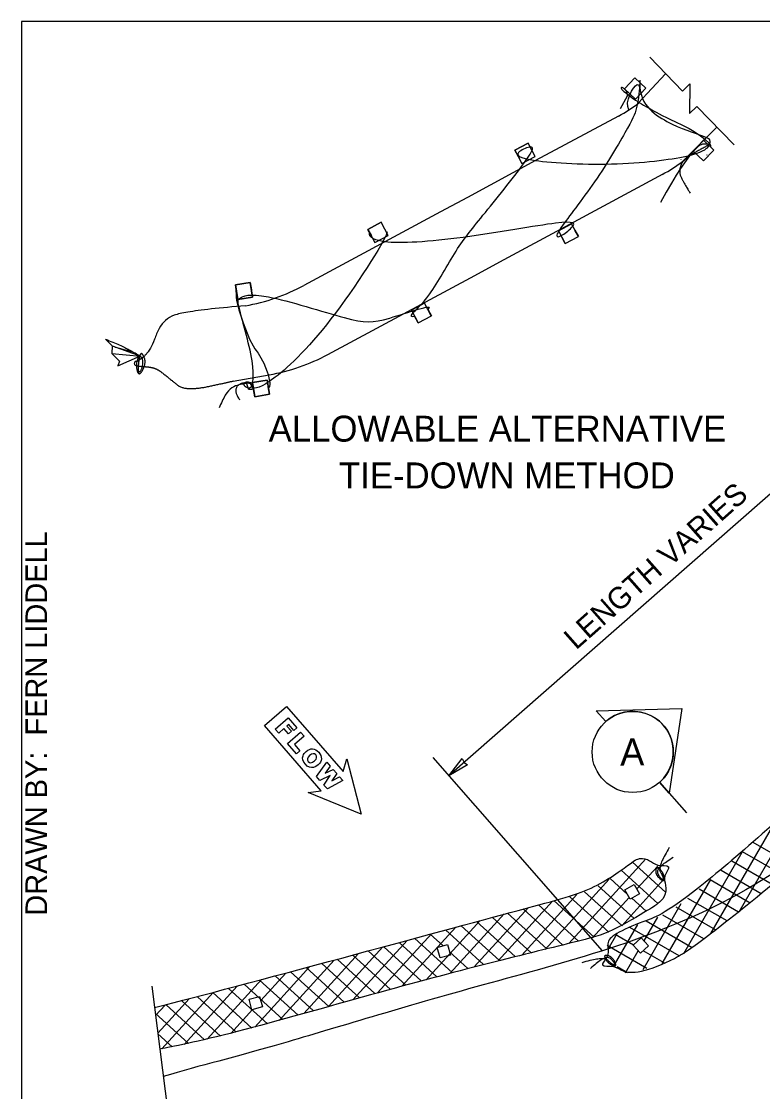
# Model space of a CAD drawing. Extents: x 99862 to 103680, y 99470 to 102076.
# Drawn here: x 99862 to 100410, y 101285 to 102076 of the extents above; entities that cross this region are included whole.
import ezdxf

# ---------------------------------------------------------------- set-up
doc = ezdxf.new("R2010")
doc.units = 0
for name, color, linetype in [('Level 1', 7, 'Continuous'), ('Level 10', 7, 'Continuous'), ('Level 15', 7, 'Continuous'), ('Level 20', 7, 'Continuous'), ('Level 4', 7, 'Continuous'), ('Level 6', 7, 'Continuous'), ('Level 62', 7, 'Continuous'), ('Level 8', 7, 'Continuous'), ('Level 9', 7, 'Continuous')]:
    doc.layers.add(name, color=color, linetype=linetype)

msp = doc.modelspace()

# ---------------------------------------------------------------- linework, layer by layer
at = {"layer": 'Level 1'}
msp.add_lwpolyline([(99862, 99999.5), (103151, 99999.5), (103151, 102075.5), (99862, 102075.5)], close=True, dxfattribs=at)
at = {"layer": 'Level 10'}
for p, q in [((100368.79, 101976.38), (100368.57, 101976.77)), ((100368.79, 101976.38), (100368.79, 101976.38)), ((100349.23, 101973.52), (100349.45, 101973.13)), ((100349.23, 101973.52), (100349.45, 101973.13)), ((100349.45, 101973.13), (100349.45, 101973.13))]:
    msp.add_line(p, q, dxfattribs=at)
for points in [[(100528.6, 101581.63), (100528.11, 101581.18), (100470.66, 101529.07), (100345.88, 101417.9), (100320.67, 101410.22), (100299.49, 101400.95), (100293.76, 101394.13), (100297.49, 101385.18), (100287.56, 101376.44), (100301.23, 101377.9), (100305.39, 101373.25), (100317.46, 101371.44), (100346.05, 101382.29), (100366.25, 101397.24), (100420.98, 101439.69), (100505.45, 101518.02), (100543.69, 101552.46), (100550.6, 101557.88)], [(99960.3, 101346.71), (99980.01, 101351.44), (100092.18, 101381.29), (100240.54, 101421.79), (100285.43, 101432.91), (100315.52, 101456.07), (100317.68, 101456.61), (100319.54, 101456.89)], [(100319.54, 101456.89), (100321.4, 101457.18), (100327.05, 101455.43), (100330.93, 101450.99), (100343.75, 101452.25), (100335.73, 101443.71), (100338.68, 101437.44), (100338.07, 101428.1), (100331.65, 101422.87), (100329.52, 101421.23), (100296.85, 101401.65), (100277.56, 101396.49), (100203.1, 101378.53), (100118.18, 101355.67), (100007.39, 101324.13), (99968.74, 101316.73), (99964.23, 101315.82)], [(100683.65, 101336.86), (100679.43, 101333.35), (100655.62, 101316.88), (100531.24, 101226.43), (100387.02, 101132.84), (100378.6, 101128.6), (100349.84, 101116.39), (100347.55, 101104.92), (100340.78, 101099.98), (100337.73, 101096.69), (100347.02, 101095.39), (100349.87, 101092.19), (100366.06, 101083.31), (100391.52, 101093.94), (100413.21, 101106.63), (100472.21, 101142.93), (100564.63, 101211.69), (100635.94, 101263.16), (100694, 101302.8), (100704.56, 101309.85)]]:
    msp.add_open_spline(points, degree=3, dxfattribs=at)
at = {"layer": 'Level 15'}
for p, q in [((100502.21, 101802.28), (100177.84, 101517.98)), ((100165.97, 101531.51), (100291.31, 101388.51))]:
    msp.add_line(p, q, dxfattribs=at)
for points in [[(100326.33, 102048.97), (100350.5, 102023.87), (100356.07, 102029.24), (100355.66, 102007.34), (100361.24, 102012.71), (100388.7, 101984.19)], [(99958.3, 101362.49), (99980, 101191.8), (99995.36, 101193.75), (99968.54, 101159.12), (99983.9, 101161.08), (100038.72, 100729.93)]]:
    msp.add_lwpolyline(points, dxfattribs=at)
msp.add_lwpolyline([(100177.84, 101517.98), (100187.64, 101530.65), (100189.12, 101527.85), (100191.7, 101526.01)], close=True, dxfattribs=at)
at = {"layer": 'Level 20'}
for p, q in [((100286.85, 101565.92), (100350.05, 101567.69)), ((100286.85, 101565.92), (100350.05, 101567.69)), ((100293.89, 101557.98), (100286.85, 101565.92)), ((100293.89, 101557.98), (100286.85, 101565.92)), ((100350.05, 101567.69), (100340.73, 101505.16)), ((100350.05, 101567.69), (100340.73, 101505.16)), ((100340.73, 101505.16), (100333.69, 101513.09)), ((100333.69, 101513.09), (100353.6, 101490.65)), ((100340.73, 101505.16), (100333.69, 101513.09)), ((100333.69, 101513.09), (100353.6, 101490.65))]:
    msp.add_line(p, q, dxfattribs=at)
for points in [[(100113.09, 101489.44), (100073.88, 101505.56), (100083.56, 101506.82), (100041.56, 101554.98), (100057.89, 101569.22), (100099.89, 101521.06), (100102.46, 101530.48), (100113.09, 101489.44)], [(100113.09, 101489.44), (100073.88, 101505.56), (100083.56, 101506.82), (100041.56, 101554.98), (100057.89, 101569.22), (100099.89, 101521.06), (100102.46, 101530.48), (100113.09, 101489.44)], [(100059.21, 101560.74), (100065.66, 101553.35), (100063.44, 101551.41), (100059.57, 101555.85), (100058.27, 101554.72), (100061.66, 101550.84), (100059.44, 101548.9), (100056.06, 101552.79), (100052.17, 101549.4), (100049.59, 101552.36), (100059.21, 101560.74)], [(100059.21, 101560.74), (100065.66, 101553.35), (100063.44, 101551.41), (100059.57, 101555.85), (100058.27, 101554.72), (100061.66, 101550.84), (100059.44, 101548.9), (100056.06, 101552.79), (100052.17, 101549.4), (100049.59, 101552.36), (100059.21, 101560.74)], [(100068.37, 101550.23), (100070.95, 101547.27), (100063.74, 101540.99), (100067.78, 101536.36), (100065.37, 101534.27), (100058.76, 101541.85), (100068.37, 101550.23)], [(100068.37, 101550.23), (100070.95, 101547.27), (100063.74, 101540.99), (100067.78, 101536.36), (100065.37, 101534.27), (100058.76, 101541.85), (100068.37, 101550.23)], [(100081.74, 101535.28), (100082.65, 101534.07), (100083.27, 101532.87), (100083.62, 101531.66), (100083.68, 101530.44), (100083.46, 101529.25), (100082.98, 101528.11), (100082.21, 101527.02), (100081.19, 101525.98), (100079.52, 101524.78), (100077.92, 101524.13), (100076.35, 101523.98), (100074.8, 101524.3), (100073.3, 101525.12), (100071.86, 101526.45), (100070.69, 101528.06), (100070.03, 101529.6), (100069.85, 101531.16), (100070.17, 101532.77), (100070.51, 101533.58), (100071, 101534.38), (100071.63, 101535.15), (100072.41, 101535.89), (100073.59, 101536.79), (100074.79, 101537.4), (100076, 101537.73), (100077.23, 101537.79), (100078.43, 101537.57), (100079.59, 101537.08), (100080.69, 101536.31), (100081.74, 101535.28)], [(100081.74, 101535.28), (100082.65, 101534.07), (100083.27, 101532.87), (100083.62, 101531.66), (100083.68, 101530.44), (100083.46, 101529.25), (100082.98, 101528.11), (100082.21, 101527.02), (100081.19, 101525.98), (100079.52, 101524.78), (100077.92, 101524.13), (100076.35, 101523.98), (100074.8, 101524.3), (100073.3, 101525.12), (100071.86, 101526.45), (100070.69, 101528.06), (100070.03, 101529.6), (100069.85, 101531.16), (100070.17, 101532.77), (100070.51, 101533.58), (100071, 101534.38), (100071.63, 101535.15), (100072.41, 101535.89), (100073.59, 101536.79), (100074.79, 101537.4), (100076, 101537.73), (100077.23, 101537.79), (100078.43, 101537.57), (100079.59, 101537.08), (100080.69, 101536.31), (100081.74, 101535.28)], [(100080.1, 101532.36), (100079.52, 101533.35), (100078.64, 101534.03), (100077.6, 101534.25), (100076.38, 101533.91), (100074.98, 101532.94), (100073.83, 101531.69), (100073.34, 101530.54), (100073.42, 101529.47), (100073.99, 101528.49), (100074.9, 101527.76), (100075.93, 101527.54), (100077.16, 101527.91), (100078.67, 101528.98), (100079.74, 101530.16), (100080.19, 101531.29), (100080.1, 101532.36)], [(100080.1, 101532.36), (100079.52, 101533.35), (100078.64, 101534.03), (100077.6, 101534.25), (100076.38, 101533.91), (100074.98, 101532.94), (100073.83, 101531.69), (100073.34, 101530.54), (100073.42, 101529.47), (100073.99, 101528.49), (100074.9, 101527.76), (100075.93, 101527.54), (100077.16, 101527.91), (100078.67, 101528.98), (100079.74, 101530.16), (100080.19, 101531.29), (100080.1, 101532.36)], [(100097.13, 101517.26), (100099.51, 101514.54), (100088.13, 101508.17), (100085.58, 101511.1), (100090.15, 101518.07), (100082.63, 101514.48), (100080.09, 101517.4), (100087.83, 101527.92), (100090.3, 101525.09), (100086.41, 101519.8), (100092.41, 101522.67), (100095.01, 101519.69), (100091.36, 101514.12), (100097.13, 101517.26)], [(100097.13, 101517.26), (100099.51, 101514.54), (100088.13, 101508.17), (100085.58, 101511.1), (100090.15, 101518.07), (100082.63, 101514.48), (100080.09, 101517.4), (100087.83, 101527.92), (100090.3, 101525.09), (100086.41, 101519.8), (100092.41, 101522.67), (100095.01, 101519.69), (100091.36, 101514.12), (100097.13, 101517.26)]]:
    msp.add_lwpolyline(points, dxfattribs=at)
msp.add_circle((100313.79, 101535.54), 30, dxfattribs=at)
msp.add_circle((100313.79, 101535.54), 30, dxfattribs=at)
msp.add_arc((100313.79, 101535.54), 30, 311.56202, 131.56645, dxfattribs=at)
msp.add_arc((100313.79, 101535.54), 30, 311.56202, 131.56645, dxfattribs=at)
at = {"layer": 'Level 4'}
for p, q in [((99929.04, 101835.59), (99950.3, 101828.19)), ((99928.77, 101830.16), (99949.94, 101828.09))]:
    msp.add_line(p, q, dxfattribs=at)
for points in [[(100304.69, 102011.18), (100309.84, 102020.58), (100309.91, 102021.75), (100309.69, 102022.69), (100308.84, 102024.07), (100307.55, 102025.62), (100306.91, 102026.25), (100305.96, 102026.72), (100305.47, 102026.61), (100305.31, 102026.44), (100305.22, 102026.07), (100305.62, 102025.24), (100306.62, 102024.29), (100307.3, 102023.75), (100308.47, 102022.88), (100309.71, 102021.96), (100310.34, 102021.48), (100312.23, 102019.98), (100314.4, 102018.34), (100315.84, 102017.34), (100317.61, 102016.18), (100318.64, 102015.53), (100320.38, 102014.47), (100321.65, 102013.71), (100324.44, 102012.09), (100325.93, 102011.25), (100329.06, 102009.51), (100331.22, 102008.33), (100335.6, 102006.02), (100338.86, 102004.37), (100341.23, 102003.2), (100345.78, 102001.03), (100350.07, 101998.99), (100355.38, 101996.3), (100357.87, 101994.9), (100362.99, 101991.57), (100365.9, 101989.38), (100367.54, 101988.01), (100369.98, 101985.68), (100370.96, 101984.42), (100371.2, 101983.91), (100371.23, 101983.03), (100370.97, 101982.47), (100370.97, 101982.47)], [(100020.68, 101877.51), (100020.65, 101877.46), (100020.59, 101876.64), (100020.58, 101876.05), (100020.59, 101874.43), (100020.78, 101871.38), (100021.01, 101869.48), (100021.62, 101866.15), (100022.07, 101864.28), (100022.63, 101862.28), (100024.07, 101857.83), (100025.9, 101852.77), (100030.6, 101840.58)], [(99924.25, 101840.61), (99929.04, 101835.59), (99928.77, 101830.16), (99934.48, 101824.37), (99933.14, 101820.82), (99950.07, 101828.32)], [(100030.6, 101840.58), (100033.23, 101835.64), (100034.62, 101833.42), (100035.42, 101832.24), (100036.86, 101830.22), (100038.97, 101826.91), (100040.25, 101824.56), (100041.05, 101822.97), (100042.48, 101819.74), (100043.67, 101816.57), (100044.32, 101814.53), (100045.22, 101810.77), (100045.52, 101808.34), (100045.54, 101807.29), (100045.3, 101805.58), (100045.04, 101804.94), (100044.59, 101804.45)]]:
    msp.add_lwpolyline(points, dxfattribs=at)
for points in [[(100307.94, 101433.6), (100314.84, 101437.65), (100318.89, 101430.75), (100311.99, 101426.7)], [(100314.19, 101392.71), (100320.13, 101398.06), (100325.49, 101392.12), (100319.54, 101386.76)], [(100169.28, 101391.08), (100177.01, 101393.15), (100179.09, 101385.43), (100171.36, 101383.35)], [(100030.31, 101352.7), (100038.03, 101354.77), (100040.11, 101347.05), (100032.39, 101344.97)]]:
    msp.add_lwpolyline(points, close=True, dxfattribs=at)
for points, degree in [([(100319.04, 102032.12), (100317.77, 102015.04), (100339.67, 101999.18), (100369.15, 101989.9), (100370.88, 101988.72), (100370.81, 101986.68)], 3), ([(100310.98, 102010.13), (100307.26, 102015.88), (100321.37, 102039.66), (100316.92, 102010.31), (100313.52, 102002.62), (100288.5, 101959.02), (100257.03, 101919.17), (100257.66, 101915.91), (100260.59, 101916.53), (100271.12, 101924.42), (100271.12, 101929.94), (100184.95, 101913.83), (100120.24, 101909.84), (100118.33, 101918.16), (100119.62, 101919.44)], 3), ([(100152.7, 101857.45), (100150.4, 101856.59), (100148.3, 101858.54), (100162.64, 101869.3), (100183.91, 101908.9), (100201.01, 101929.41), (100241.32, 101979.51), (100240.06, 101984.24), (100228.4, 101979.59), (100226.82, 101972.75), (100300, 101967.97), (100362.31, 101976.02), (100371.2, 101983.91), (100370.47, 101985.05), (100358.18, 101985.05), (100334.25, 101941.68)], 3), ([(100370.81, 101986.68), (100370.96, 101984.42), (100357.34, 101977.45), (100351.09, 101972.41), (100349.42, 101969.8), (100348.08, 101963.98), (100350.31, 101958.23), (100356.23, 101948.66)], 2), ([(100827.57, 101924.36), (100760.06, 101847.66), (100689.54, 101753.7), (100669.26, 101721.45), (100565.8, 101567.25), (100397.3, 101413.08), (100195.24, 101363.06), (100041.72, 101315.14), (99995.15, 101304.04), (99966.8, 101295.66)], 3), ([(100132.19, 101919.85), (100133.03, 101917.24), (100091.69, 101851.07), (100044.45, 101805.23), (100028.42, 101802.85), (100037.31, 101812.21), (100021.01, 101869.48), (100022.01, 101869.87), (100033.65, 101877.28), (100110.92, 101852.48), (100126.41, 101852.48), (100167.95, 101867.66), (100162.42, 101862.68)], 3), ([(100027.49, 101865.36), (99987.04, 101861.93), (99965.72, 101855.62), (99957.29, 101831.72), (99948.11, 101824.17), (99945.45, 101824.17), (99945.45, 101820.84), (99952.98, 101820.4), (99957.69, 101819.92), (99963.06, 101818.32), (99973.27, 101810.03), (99980.29, 101804.16), (99993.01, 101804.06), (100011.68, 101808.18), (100018.93, 101809.78)], 2), ([(99924.25, 101840.61), (99950.11, 101830.2), (99946.24, 101822.9), (99948.66, 101812.44), (99954.47, 101823.06), (99952.84, 101826.87)], 2), ([(99952.84, 101826.87), (99951.3, 101830.91), (99948.95, 101828.41), (99947.88, 101814.48), (99952.02, 101819.68), (99951.32, 101830.3), (99931.4, 101834.45)], 2), ([(100032.8, 101807.81), (100029.39, 101809), (100028.07, 101808.8), (100026.38, 101808.01), (100026.32, 101806.4), (100028.33, 101805.22), (100030.2, 101804.33), (100032.53, 101805.63), (100031.03, 101808.07), (100027.91, 101808.07), (100013.89, 101804.52), (100008.05, 101789.91)], 2), ([(100033.46, 101803.82), (100031.1, 101803.23), (100029.64, 101803.48), (100028.62, 101808.78), (100021.62, 101807.14), (100019.64, 101800.77), (100023.29, 101795.89)], 2), ([(101085.75, 101767.26), (100851.58, 101567.5), (100738.84, 101387.48), (100680.23, 101288.16), (100628.41, 101241.49), (100408.17, 101099.51), (100270.3, 101083.42), (100093.57, 101042.42), (100035.51, 101028.27), (100002.7, 101021.57)], 3), ([(100340.76, 101464.9), (100332.05, 101450.3), (100336.44, 101446.34), (100337.38, 101438.72), (100330.87, 101444.44), (100331.03, 101447.4)], 2), ([(100331.03, 101447.4), (100331.08, 101450.49), (100333.27, 101449.38), (100337.4, 101440.29), (100333.34, 101442.77), (100331.21, 101450.07), (100343.58, 101457.73)], 2), ([(100276.35, 101380.02), (100292.73, 101384.58), (100295.39, 101379.3), (100302.5, 101376.38), (100298.7, 101384.16), (100295.8, 101384.79)], 2), ([(100295.8, 101384.79), (100292.81, 101385.56), (100293.3, 101383.15), (100300.98, 101376.77), (100299.66, 101381.34), (100293.17, 101385.32), (100282.53, 101375.41)], 2)]:
    msp.add_open_spline(points, degree=degree, dxfattribs=at)
at = {"layer": 'Level 6'}
for p, q in [((100315.36, 102033.72), (100307.8, 102025.68)), ((100323.4, 102026.16), (100315.36, 102033.72)), ((100307.8, 102025.68), (100315.84, 102018.12)), ((100315.84, 102018.12), (100323.4, 102026.16)), ((100317.27, 102028.65), (100317.27, 102028.65)), ((100226.71, 101980.22), (100236.43, 101985.46)), ((100236.43, 101985.45), (100226.72, 101980.22)), ((100236.43, 101985.45), (100236.43, 101985.46)), ((100236.43, 101985.46), (100239.04, 101980.61)), ((100236.43, 101985.45), (100236.43, 101985.46)), ((100241.66, 101975.76), (100236.43, 101985.45)), ((100226.71, 101980.22), (100226.72, 101980.22)), ((100229.32, 101975.38), (100226.71, 101980.22)), ((100226.71, 101980.22), (100226.72, 101980.22)), ((100226.72, 101980.22), (100231.94, 101970.52)), ((100231.94, 101970.52), (100241.66, 101975.76)), ((100241.66, 101975.76), (100241.66, 101975.76)), ((100231.94, 101970.52), (100231.94, 101970.52)), ((100118.05, 101921.76), (100127.77, 101927)), ((100118.05, 101921.76), (100118.06, 101921.76)), ((100118.05, 101921.76), (100118.05, 101921.76)), ((100120.66, 101916.92), (100118.05, 101921.76)), ((100127.77, 101926.99), (100118.06, 101921.76)), ((100118.06, 101921.76), (100123.31, 101912)), ((100118.08, 101921.7), (100118.08, 101921.7)), ((100127.77, 101926.99), (100127.77, 101927)), ((100127.77, 101927), (100130.38, 101922.15)), ((100127.77, 101926.99), (100127.77, 101926.99)), ((100133.03, 101917.24), (100127.77, 101926.99)), ((100127.8, 101926.94), (100127.8, 101926.94)), ((100258.82, 101920.64), (100268.53, 101925.88)), ((100271, 101921.31), (100273.61, 101916.46)), ((100123.31, 101912), (100133.03, 101917.24)), ((100133.03, 101917.24), (100133.03, 101917.24)), ((100263.89, 101911.23), (100261.28, 101916.07)), ((100263.89, 101911.23), (100273.6, 101916.47)), ((100123.31, 101912), (100123.31, 101912)), ((100020.12, 101880.75), (100030.99, 101882.64)), ((100020.12, 101880.74), (100030.99, 101882.63)), ((100030.99, 101882.63), (100020.12, 101880.74)), ((100020.12, 101880.75), (100020.12, 101880.74)), ((100021.06, 101875.32), (100020.12, 101880.75)), ((100020.12, 101880.74), (100020.12, 101880.74)), ((100022.01, 101869.87), (100020.12, 101880.74)), ((100020.12, 101880.74), (100022.01, 101869.87)), ((100020.12, 101880.72), (100020.12, 101880.72)), ((100030.99, 101882.63), (100030.99, 101882.64)), ((100030.99, 101882.64), (100031.94, 101877.21)), ((100030.99, 101882.63), (100030.99, 101882.63)), ((100030.99, 101882.63), (100032.89, 101871.76)), ((100032.89, 101871.76), (100030.99, 101882.63)), ((100031, 101882.61), (100031, 101882.61)), ((100032.89, 101871.76), (100022.01, 101869.87)), ((100022.01, 101869.87), (100032.89, 101871.76)), ((100022.01, 101869.87), (100022.01, 101869.87)), ((100032.89, 101871.76), (100032.89, 101871.76)), ((100155.23, 101852.76), (100152.62, 101857.61)), ((100162.33, 101862.84), (100164.95, 101858)), ((100032.67, 101808.55), (100043.55, 101810.44)), ((100043.55, 101810.44), (100032.67, 101808.55)), ((100032.67, 101808.55), (100034.49, 101798.12)), ((100034.49, 101798.11), (100033.54, 101803.54)), ((100044.42, 101805.43), (100045.36, 101800)), ((100045.36, 101800.01), (100034.49, 101798.12)), ((100034.49, 101798.12), (100045.36, 101800.01)), ((100045.36, 101800.01), (100045.36, 101800.01))]:
    msp.add_line(p, q, dxfattribs=at)
for points in [[(100239.04, 101980.61), (100239.04, 101980.61), (100236.43, 101985.46)], [(100236.43, 101985.46), (100236.43, 101985.46), (100236.43, 101985.46)], [(100366.02, 101987.69), (100373.73, 101980.43), (100373.74, 101980.43), (100366.18, 101972.39), (100366.17, 101972.39), (100358.46, 101979.65), (100366.02, 101987.69)], [(100226.71, 101980.22), (100229.32, 101975.38), (100229.32, 101975.38)], [(100226.71, 101980.22), (100226.71, 101980.22), (100226.71, 101980.22)], [(100118.05, 101921.76), (100120.66, 101916.92), (100120.66, 101916.92)], [(100130.38, 101922.15), (100130.38, 101922.15), (100127.77, 101926.99)], [(100258.82, 101920.64), (100263.89, 101911.23), (100263.89, 101911.23), (100273.61, 101916.46), (100273.6, 101916.47), (100268.53, 101925.88), (100258.82, 101920.64)], [(100258.82, 101920.64), (100258.82, 101920.64), (100263.89, 101911.23), (100263.89, 101911.23)], [(100273.6, 101916.46), (100273.6, 101916.46), (100268.53, 101925.88), (100268.53, 101925.88)], [(100273.6, 101916.46), (100273.6, 101916.46), (100271, 101921.31)], [(100261.28, 101916.07), (100263.89, 101911.23), (100263.89, 101911.23)], [(100020.12, 101880.74), (100021.06, 101875.32), (100021.06, 101875.32)], [(100031.94, 101877.21), (100031.94, 101877.21), (100030.99, 101882.63)], [(100150.19, 101862.12), (100155.22, 101852.77), (100155.23, 101852.76), (100164.95, 101858), (100164.94, 101858), (100159.9, 101867.36), (100150.19, 101862.12)], [(100152.62, 101857.61), (100155.23, 101852.77), (100155.23, 101852.77)], [(100164.94, 101858), (100164.94, 101858), (100162.33, 101862.84)], [(100032.67, 101808.55), (100034.49, 101798.12), (100034.49, 101798.11), (100045.36, 101800), (100045.36, 101800.01), (100043.55, 101810.44), (100032.67, 101808.55)], [(100043.55, 101810.44), (100043.55, 101810.44), (100045.36, 101800.01), (100045.36, 101800.01)], [(100045.36, 101800.01), (100045.36, 101800.01), (100043.55, 101810.44), (100043.55, 101810.44)], [(100034.49, 101798.11), (100034.49, 101798.11), (100032.67, 101808.55), (100032.67, 101808.55)], [(100032.67, 101808.55), (100032.67, 101808.55), (100034.49, 101798.11), (100034.49, 101798.11)], [(100033.54, 101803.54), (100034.49, 101798.11), (100034.49, 101798.11)], [(100045.36, 101800.01), (100045.36, 101800.01), (100044.42, 101805.43)]]:
    msp.add_lwpolyline(points, dxfattribs=at)
at = {"layer": 'Level 8'}
for points in [[(100338.1, 102036.75), (100317.77, 102015.04)], [(100303.28, 102005.57), (100242.01, 101972.57), (100191.66, 101945.44)], [(100351.09, 101972.41), (100376.04, 101997.31)], [(100215.68, 101897.84), (100267.29, 101925.64), (100336.18, 101962.75)], [(100191.66, 101945.44), (100171.76, 101934.72), (100070.83, 101880.36)], [(100088.51, 101829.34), (100197.04, 101887.8), (100215.68, 101897.84)], [(100018.53, 101809.71), (100045.15, 101814.34)]]:
    msp.add_lwpolyline(points, dxfattribs=at)
for centre, radius, start, end in [((100250.94, 102102.75), 110.38, 298.31028, 307.59396), ((100283.53, 102059.69), 110.38, 298.12643, 307.74176), ((100002.98, 102006.32), 143.08, 279.8639, 298.31029), ((100020.66, 101955.31), 143.08, 279.85568, 298.31028)]:
    msp.add_arc(centre, radius, start, end, dxfattribs=at)
at = {"layer": 'Level 9'}
for p, q in [((100392.36, 101417.49), (100442.15, 101503.74)), ((100371.53, 101401.42), (100418.3, 101482.42)), ((100351.44, 101386.62), (100394.6, 101461.37)), ((100424.95, 101444.39), (100394.97, 101461.7)), ((100432.9, 101451.35), (100402.88, 101468.68)), ((100266.54, 101393.88), (100323.57, 101456.49)), ((100313.4, 101454.24), (100338.25, 101431.61)), ((100416.91, 101437.49), (100387.03, 101454.74)), ((100305.24, 101448.15), (100332.36, 101423.45)), ((100316.84, 101434.25), (100332.06, 101450.97)), ((100331.62, 101451.18), (100333.64, 101449.34)), ((100408.76, 101430.64), (100379.03, 101447.81)), ((100249.16, 101389.65), (100296.49, 101441.62)), ((100297.1, 101442.03), (100309.75, 101430.51)), ((100305.64, 101407.11), (100336.87, 101441.39)), ((100335.6, 101379.18), (100371.5, 101441.36)), ((100400.48, 101423.88), (100370.98, 101440.91)), ((100231.81, 101385.44), (100272.45, 101430.07)), ((100278.25, 101432.16), (100305.71, 101407.15)), ((100288.16, 101436.66), (100314.79, 101412.4)), ((100392.01, 101417.22), (100362.82, 101434.07)), ((100214.33, 101381.1), (100254.49, 101425.2)), ((100244.26, 101422.53), (100273.77, 101395.66)), ((100255.81, 101425.54), (100285.4, 101398.59)), ((100267.39, 101428.52), (100296.13, 101402.35)), ((100284.04, 101398.24), (100311.2, 101428.06)), ((100313.18, 101427.4), (100323.73, 101417.79)), ((100321.44, 101374.65), (100349.6, 101423.44)), ((100383.47, 101410.61), (100354.53, 101427.31)), ((100178.98, 101371.99), (100218.86, 101415.77)), ((100196.72, 101376.62), (100236.73, 101420.54)), ((100221.27, 101416.42), (100250.35, 101389.93)), ((100232.75, 101419.49), (100262.07, 101392.78)), ((100366.31, 101397.42), (100336.15, 101414.83)), ((100374.9, 101404.01), (100345.99, 101420.7)), ((100143.17, 101362.37), (100182.96, 101406.07)), ((100161.13, 101367.23), (100200.93, 101410.94)), ((100186.9, 101407.14), (100215.24, 101381.33)), ((100198.35, 101410.24), (100226.9, 101384.24)), ((100209.8, 101413.34), (100238.61, 101387.1)), ((100300.42, 101378.24), (100317.63, 101408.05)), ((100348.2, 101384.78), (100311.67, 101405.87)), ((100322.13, 101395.85), (100332.24, 101413.35)), ((100357.65, 101390.87), (100323.82, 101410.4)), ((100125.13, 101357.41), (100164.97, 101401.16)), ((100164.04, 101400.91), (100173.57, 101392.23)), ((100175.47, 101404.03), (100203.62, 101378.39)), ((100295.56, 101389.83), (100302.23, 101401.39)), ((100314.3, 101392.81), (100300.78, 101400.61)), ((100088.86, 101347.29), (100129.02, 101391.38)), ((100107.02, 101352.38), (100146.99, 101396.26)), ((100129.73, 101391.58), (100157.53, 101366.26)), ((100141.17, 101394.68), (100169, 101369.34)), ((100152.61, 101397.79), (100180.5, 101372.39)), ((100324.3, 101375.48), (100294.92, 101392.45)), ((100070.65, 101342.14), (100111.07, 101386.53)), ((100095.37, 101382.29), (100123.26, 101356.89)), ((100106.83, 101385.38), (100134.66, 101360.04)), ((100118.28, 101388.48), (100146.08, 101363.16)), ((100178.45, 101387.78), (100192.04, 101375.41)), ((100308.55, 101372.33), (100317.92, 101388.56)), ((100336.99, 101379.71), (100321.58, 101388.6)), ((100034.42, 101332.06), (100075.22, 101376.87)), ((100052.43, 101336.98), (100093.14, 101381.69)), ((100072.44, 101376.12), (100100.51, 101350.56)), ((100083.91, 101379.2), (100111.88, 101353.73)), ((100309.95, 101372.22), (100302.26, 101376.66)), ((99999.29, 101323.19), (100039.44, 101367.28)), ((100038.02, 101366.9), (100066.5, 101340.96)), ((100038.84, 101351.77), (100057.32, 101372.06)), ((100049.5, 101369.97), (100077.82, 101344.17)), ((100060.97, 101373.04), (100089.16, 101347.37)), ((99982.32, 101319.41), (100021.57, 101362.5)), ((100015.05, 101360.77), (100043.78, 101334.59)), ((100026.53, 101363.83), (100055.17, 101337.75)), ((99962.73, 101327.6), (99985.89, 101353.03)), ((99965.85, 101316.18), (100003.71, 101357.75)), ((99980.53, 101351.63), (100009.15, 101325.56)), ((99992.05, 101354.66), (100020.79, 101328.49)), ((100003.55, 101357.71), (100032.33, 101331.5)), ((99961.07, 101340.64), (99968.15, 101348.4)), ((99968.98, 101348.62), (99997.39, 101322.75)), ((100016.68, 101327.44), (100032.73, 101345.06)), ((99960.84, 101342.51), (99985.46, 101320.08)), ((99962.78, 101327.21), (99973.33, 101317.61))]:
    msp.add_line(p, q, dxfattribs=at)

# ---------------------------------------------------------------- texts
at = {"layer": 'Level 20'}
for s, p in [('ALLOWABLE ALTERNATIVE ', (100044.71, 101764.89)), ('TIE-DOWN METHOD', (100096.68, 101730.33))]:
    msp.add_text(s, height=19.2, dxfattribs=at).set_placement(p)
for s, height, rotation, p in [('LENGTH VARIES', 16, 41.51375, (100271.88, 101610.48)), ('A', 20, 0.0894, (100304.56, 101525.52))]:
    msp.add_text(s, height=height, rotation=rotation, dxfattribs=at).set_placement(p)
at = {"layer": 'Level 62'}
msp.add_text('DRAWN BY:  FERN LIDDELL', height=16, rotation=90, dxfattribs=at).set_placement((99881, 101414.52))

doc.saveas('drawing.dxf')
